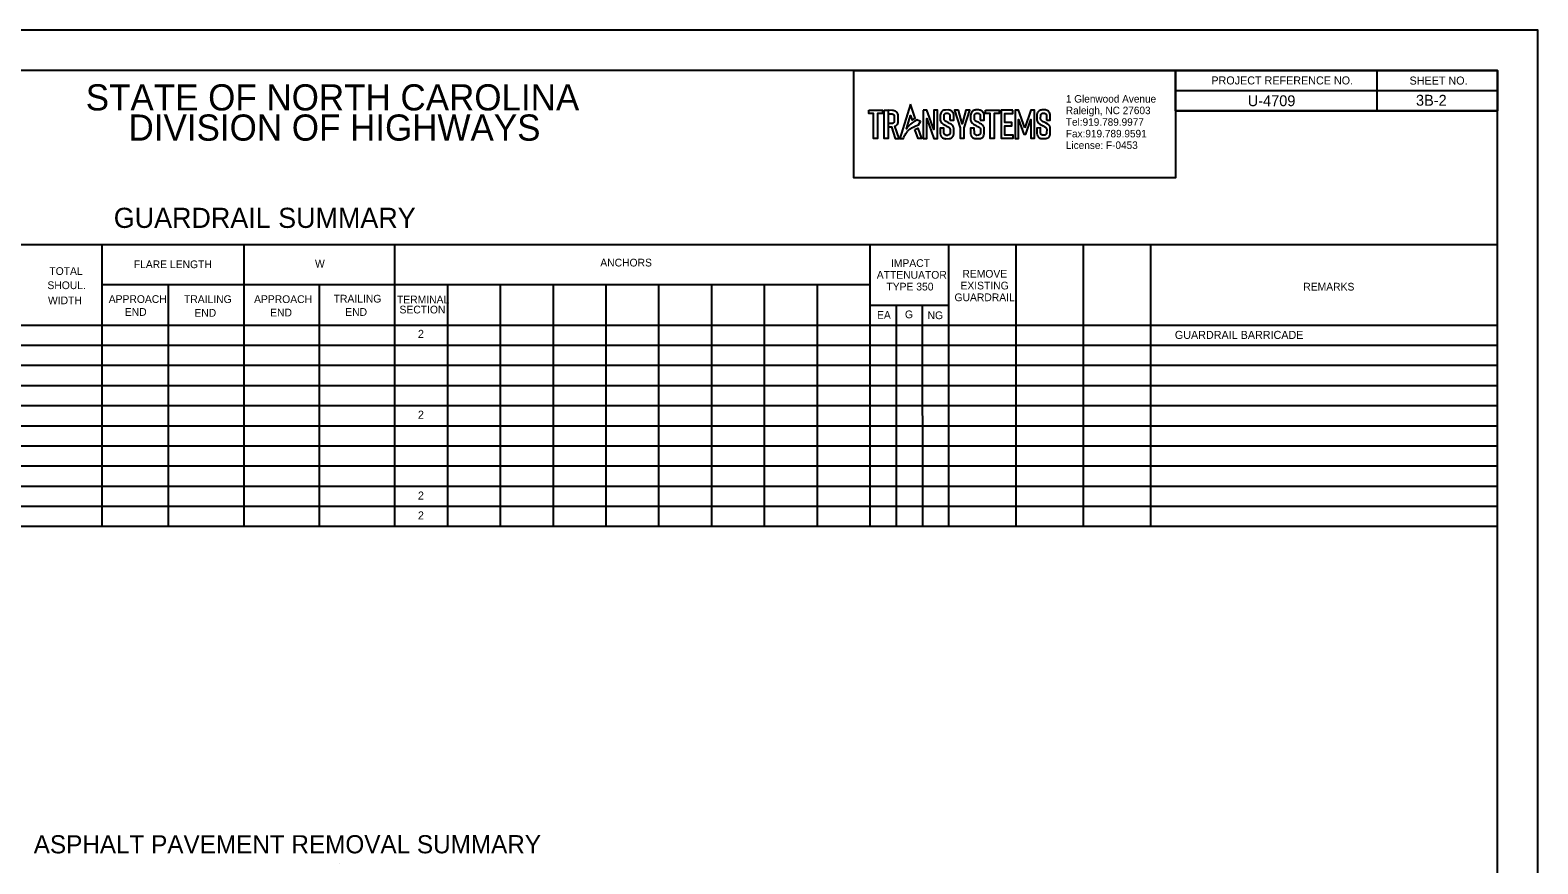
# Model space of a CAD drawing. Extents: x 573680 to 576464, y -53324 to -52224.
# Drawn here: x 574443 to 575380, y -52742 to -52224 of the extents above; entities that cross this region are included whole.
import ezdxf

# ---------------------------------------------------------------- set-up
doc = ezdxf.new("R2010")
doc.units = 0
for name, color, linetype in [('Old_Level_1', 7, 'Continuous'), ('Old_Level_2', 7, 'Continuous'), ('Old_Level_58', 7, 'Continuous'), ('Sheet Data Field CELL', 7, 'Continuous'), ('Sheet Plan And Profile CELL', 7, 'Continuous'), ('Sheet Plot Border Outside CELL', 7, 'Continuous'), ('Sheet Summary Combination CELL', 7, 'Continuous'), ('Sheet Summary Combination Grid CELL', 7, 'Continuous')]:
    doc.layers.add(name, color=color, linetype=linetype)

msp = doc.modelspace()

# ---------------------------------------------------------------- linework, layer by layer
at = {"layer": 'Old_Level_1'}
for points in [[(574990.11, -52270.23), (574983.45, -52291.56), (574985.67, -52291.55), (574986.01, -52290.71), (574986.59, -52289.55), (574986.9, -52288.92), (574987.27, -52288.39), (574987.8, -52287.63), (574988.12, -52287.16), (574988.5, -52286.77), (574988.88, -52286.37), (574989.37, -52285.88), (574989.78, -52285.61), (574990.2, -52285.27), (574990.75, -52284.95), (574991.25, -52284.67), (574992.46, -52284.1), (574993.46, -52283.69), (574995.11, -52283.13), (574996.24, -52280.99), (574994.07, -52280.04), (574992.43, -52280.92), (574991.06, -52281.83), (574990.08, -52282.62), (574989.55, -52283.05), (574989.02, -52283.62), (574988.48, -52284.18), (574988.08, -52284.61), (574987.71, -52285.26), (574987.5, -52285.62), (574990.13, -52277.24), (574991.12, -52280.13), (574993.02, -52278.87)], [(574964.15, -52274.08), (574972.62, -52274.07), (574972.62, -52276.14), (574969.51, -52276.15), (574969.52, -52291.57), (574967.17, -52291.57), (574967.16, -52276.04), (574964.19, -52276.05)], [(574973.77, -52274.08), (574976.09, -52274.08), (574976.1, -52291.64), (574973.79, -52291.65)], [(574976.09, -52276.16), (574978.48, -52276.16), (574978.78, -52276.21), (574979.18, -52276.38), (574979.5, -52276.59), (574979.74, -52276.87), (574979.89, -52277.2), (574980.01, -52277.45), (574980.01, -52278.03), (574980.02, -52280.52), (574979.96, -52280.85), (574979.88, -52281.3), (574979.75, -52281.59), (574979.55, -52281.85), (574979.28, -52282.07), (574978.85, -52282.22), (574978.53, -52282.26), (574978.2, -52282.3), (574976.09, -52282.31), (574976.1, -52284.42), (574978.21, -52284.41), (574980.58, -52291.57), (574983, -52291.55), (574980.35, -52284.01), (574980.73, -52283.87), (574981.26, -52283.47), (574981.75, -52282.94), (574982.1, -52282.31), (574982.31, -52281.67), (574982.3, -52281.49), (574982.34, -52276.92), (574982.14, -52276.18), (574981.77, -52275.5), (574981.36, -52275.03), (574980.66, -52274.55), (574979.99, -52274.33), (574979.31, -52274.1), (574978.9, -52274.1), (574976.09, -52274.08)], [(574997.88, -52274.04), (574997.9, -52291.5), (575000.13, -52291.5), (575000.12, -52279.22), (575004.58, -52291.53), (575006.83, -52291.5), (575006.8, -52273.99), (575004.63, -52274), (575004.64, -52285.98), (575000.24, -52274.04)], [(575014.58, -52280.22), (575016.89, -52280.21), (575016.89, -52276.74), (575016.69, -52276.03), (575016.41, -52275.44), (575016.11, -52275.05), (575015.74, -52274.7), (575015.3, -52274.42), (575014.88, -52274.24), (575014.88, -52274.24), (575014.42, -52274.05), (575013.94, -52273.93), (575013.62, -52273.85), (575011.87, -52273.88), (575011.34, -52273.97), (575010.88, -52274.05), (575010.42, -52274.29), (575010.01, -52274.5), (575009.62, -52274.79), (575009.31, -52275.1), (575009.07, -52275.47), (575008.87, -52275.86), (575008.62, -52276.56), (575008.57, -52277.07), (575008.57, -52280.24), (575008.68, -52280.72), (575008.91, -52281.21), (575009.2, -52281.62), (575009.5, -52281.93), (575009.95, -52282.28), (575010.4, -52282.63), (575010.69, -52282.85), (575011.17, -52283.07), (575011.65, -52283.3), (575012.04, -52283.55), (575012.48, -52283.84), (575013.01, -52284.11), (575013.44, -52284.32), (575013.87, -52284.64), (575014.18, -52284.93), (575014.43, -52285.17), (575014.59, -52285.65), (575014.68, -52285.95), (575014.65, -52288.19), (575014.49, -52288.67), (575014.24, -52289.09), (575013.91, -52289.38), (575013.56, -52289.54), (575013.22, -52289.62), (575012.25, -52289.64), (575011.93, -52289.55), (575011.6, -52289.35), (575011.27, -52289.16), (575011.13, -52288.82), (575010.99, -52288.49), (575010.88, -52288.22), (575010.84, -52285.11), (575008.5, -52285.14), (575008.55, -52288.85), (575008.66, -52289.13), (575008.93, -52289.99), (575009.11, -52290.28), (575009.36, -52290.6), (575009.74, -52290.98), (575010.05, -52291.17), (575010.48, -52291.35), (575010.64, -52291.42), (575011.07, -52291.6), (575011.6, -52291.65), (575012, -52291.69), (575014.14, -52291.64), (575014.73, -52291.5), (575015.56, -52291.12), (575015.84, -52291), (575016.46, -52290.21), (575016.79, -52289.42), (575016.95, -52288.71), (575016.9, -52285.29), (575016.89, -52284.81), (575016.76, -52284.44), (575016.57, -52284.08), (575016.03, -52283.33), (575015.32, -52282.77), (575014.34, -52282.19), (575013.6, -52281.75), (575012.14, -52280.98), (575011.38, -52280.42), (575011.05, -52280), (575010.98, -52279.71), (575010.9, -52279.43), (575010.94, -52277), (575011.07, -52276.74), (575011.19, -52276.49), (575011.37, -52276.33), (575011.6, -52276.14), (575011.86, -52276.03), (575012.12, -52275.92), (575012.27, -52275.95), (575012.28, -52275.88), (575013.24, -52275.89), (575013.52, -52276), (575013.79, -52276.11), (575014.07, -52276.22), (575014.2, -52276.42), (575014.39, -52276.69), (575014.48, -52276.97), (575014.57, -52277.25), (575014.56, -52277.55)], [(575019.85, -52274.03), (575017.31, -52274.04), (575020.93, -52284.92), (575020.96, -52291.46), (575023.35, -52291.45), (575023.32, -52284.96), (575026.98, -52273.99), (575024.49, -52274.06), (575022.18, -52282.4)], [(575033.45, -52280.2), (575035.76, -52280.2), (575035.76, -52276.72), (575035.56, -52276.01), (575035.28, -52275.42), (575034.98, -52275.03), (575034.61, -52274.68), (575034.17, -52274.4), (575033.75, -52274.22), (575033.75, -52274.22), (575033.29, -52274.03), (575032.81, -52273.91), (575032.49, -52273.83), (575030.74, -52273.87), (575030.21, -52273.96), (575029.75, -52274.04), (575029.29, -52274.28), (575028.89, -52274.49), (575028.49, -52274.77), (575028.18, -52275.08), (575027.94, -52275.45), (575027.74, -52275.84), (575027.49, -52276.54), (575027.44, -52277.06), (575027.44, -52280.23), (575027.56, -52280.7), (575027.78, -52281.2), (575028.07, -52281.61), (575028.37, -52281.92), (575028.82, -52282.26), (575029.27, -52282.61), (575029.56, -52282.83), (575030.04, -52283.06), (575030.52, -52283.28), (575030.91, -52283.53), (575031.36, -52283.82), (575031.88, -52284.09), (575032.32, -52284.31), (575032.75, -52284.62), (575033.06, -52284.92), (575033.31, -52285.15), (575033.46, -52285.64), (575033.55, -52285.93), (575033.52, -52288.17), (575033.36, -52288.65), (575033.11, -52289.07), (575032.78, -52289.37), (575032.43, -52289.53), (575032.09, -52289.6), (575031.13, -52289.62), (575030.8, -52289.53), (575030.48, -52289.33), (575030.15, -52289.14), (575030, -52288.81), (575029.86, -52288.47), (575029.75, -52288.2), (575029.71, -52285.09), (575027.37, -52285.12), (575027.42, -52288.83), (575027.54, -52289.11), (575027.81, -52289.97), (575027.98, -52290.27), (575028.23, -52290.58), (575028.61, -52290.96), (575028.92, -52291.15), (575029.35, -52291.33), (575029.51, -52291.4), (575029.94, -52291.58), (575030.48, -52291.64), (575030.87, -52291.67), (575033.01, -52291.62), (575033.6, -52291.48), (575034.43, -52291.11), (575034.71, -52290.98), (575035.33, -52290.19), (575035.67, -52289.4), (575035.82, -52288.69), (575035.77, -52285.27), (575035.76, -52284.8), (575035.63, -52284.42), (575035.44, -52284.07), (575034.9, -52283.31), (575034.19, -52282.75), (575033.22, -52282.17), (575032.47, -52281.73), (575031.01, -52280.96), (575030.25, -52280.4), (575029.93, -52279.98), (575029.85, -52279.69), (575029.77, -52279.41), (575029.82, -52276.98), (575029.94, -52276.72), (575030.06, -52276.47), (575030.24, -52276.32), (575030.47, -52276.12), (575030.73, -52276.01), (575030.99, -52275.91), (575031.14, -52275.94), (575031.15, -52275.86), (575032.11, -52275.88), (575032.39, -52275.99), (575032.67, -52276.1), (575032.94, -52276.21), (575033.07, -52276.4), (575033.26, -52276.68), (575033.35, -52276.95), (575033.44, -52277.23), (575033.44, -52277.53)], [(575036.61, -52274.01), (575045.08, -52274), (575045.08, -52276.08), (575041.97, -52276.08), (575041.98, -52291.5), (575039.63, -52291.5), (575039.62, -52275.98), (575036.65, -52275.98)], [(575053.68, -52274), (575046.3, -52274.01), (575046.31, -52291.44), (575053.78, -52291.43), (575053.78, -52289.46), (575048.74, -52289.46), (575048.73, -52283.62), (575052.95, -52283.62), (575052.95, -52281.54), (575048.69, -52281.54), (575048.69, -52276.05), (575053.7, -52276.04)], [(575061.06, -52284.85), (575057.25, -52273.93), (575055.03, -52274.04), (575055.12, -52291.5), (575057.23, -52291.49), (575057.17, -52279.81), (575060.44, -52288.8), (575061.79, -52288.83), (575064.85, -52279.7), (575064.9, -52291.42), (575067.18, -52291.41), (575067.11, -52273.99), (575064.81, -52274)], [(575074.58, -52280.16), (575076.9, -52280.16), (575076.89, -52276.68), (575076.7, -52275.98), (575076.42, -52275.39), (575076.12, -52275), (575075.75, -52274.64), (575075.31, -52274.36), (575074.88, -52274.19), (575074.88, -52274.19), (575074.42, -52273.99), (575073.94, -52273.87), (575073.62, -52273.79), (575071.87, -52273.83), (575071.34, -52273.92), (575070.88, -52274), (575070.42, -52274.24), (575070.02, -52274.45), (575069.62, -52274.73), (575069.31, -52275.05), (575069.07, -52275.41), (575068.88, -52275.81), (575068.62, -52276.5), (575068.57, -52277.02), (575068.57, -52280.19), (575068.69, -52280.66), (575068.92, -52281.16), (575069.21, -52281.57), (575069.5, -52281.88), (575069.95, -52282.23), (575070.41, -52282.57), (575070.69, -52282.79), (575071.17, -52283.02), (575071.66, -52283.24), (575072.05, -52283.5), (575072.49, -52283.78), (575073.02, -52284.05), (575073.45, -52284.27), (575073.88, -52284.58), (575074.19, -52284.88), (575074.44, -52285.12), (575074.59, -52285.6), (575074.69, -52285.9), (575074.65, -52288.13), (575074.49, -52288.62), (575074.24, -52289.04), (575073.92, -52289.33), (575073.56, -52289.49), (575073.22, -52289.56), (575072.26, -52289.58), (575071.94, -52289.49), (575071.61, -52289.3), (575071.28, -52289.1), (575071.14, -52288.77), (575070.99, -52288.43), (575070.88, -52288.17), (575070.84, -52285.05), (575068.51, -52285.08), (575068.55, -52288.79), (575068.67, -52289.07), (575068.94, -52289.93), (575069.11, -52290.23), (575069.37, -52290.55), (575069.75, -52290.92), (575070.05, -52291.11), (575070.49, -52291.3), (575070.64, -52291.36), (575071.07, -52291.54), (575071.61, -52291.6), (575072, -52291.64), (575074.14, -52291.58), (575074.74, -52291.44), (575075.56, -52291.07), (575075.84, -52290.94), (575076.46, -52290.15), (575076.8, -52289.36), (575076.95, -52288.65), (575076.9, -52285.23), (575076.89, -52284.76), (575076.76, -52284.38), (575076.57, -52284.03), (575076.03, -52283.27), (575075.32, -52282.71), (575074.35, -52282.13), (575073.6, -52281.69), (575072.14, -52280.92), (575071.39, -52280.36), (575071.06, -52279.94), (575070.98, -52279.66), (575070.9, -52279.37), (575070.95, -52276.94), (575071.07, -52276.69), (575071.2, -52276.43), (575071.37, -52276.28), (575071.61, -52276.08), (575071.86, -52275.98), (575072.12, -52275.87), (575072.27, -52275.9), (575072.29, -52275.82), (575073.24, -52275.84), (575073.52, -52275.95), (575073.8, -52276.06), (575074.08, -52276.17), (575074.21, -52276.36), (575074.39, -52276.64), (575074.48, -52276.91), (575074.58, -52277.19), (575074.57, -52277.5)], [(574992.73, -52285.93), (574994.64, -52285.17), (574996.91, -52291.61), (574994.81, -52291.53)]]:
    msp.add_lwpolyline(points, close=True, dxfattribs=at)
at = {"layer": 'Old_Level_58'}
msp.add_lwpolyline([(574954.76, -52249.31), (575154.81, -52249.31), (575154.81, -52316), (574954.76, -52316)], close=True, dxfattribs=at)
at = {"layer": 'Sheet Plan And Profile CELL'}
for points in [[(575354.86, -52249.31), (573854.86, -52249.31), (573854.86, -53299.31), (575354.86, -53299.31)], [(575154.81, -52249.31), (575354.86, -52249.31), (575354.86, -52274.36), (575154.81, -52274.36)]]:
    msp.add_lwpolyline(points, close=True, dxfattribs=at)
at = {"layer": 'Sheet Plot Border Outside CELL'}
msp.add_lwpolyline([(573679.86, -53324.31), (575379.86, -53324.31), (575379.86, -52224.31), (573679.86, -52224.31)], close=True, dxfattribs=at)
at = {"layer": 'Sheet Summary Combination CELL'}
for p, q in [((575279.86, -52249.36), (575279.86, -52274.36)), ((575154.81, -52261.86), (575354.86, -52261.86)), ((575154.81, -52274.36), (575354.86, -52274.36)), ((574635.06, -52741.93), (574635.06, -52741.93))]:
    msp.add_line(p, q, dxfattribs=at)
msp.add_lwpolyline([(575154.81, -52249.31), (575354.86, -52249.31), (575354.86, -52274.36), (575154.81, -52274.36)], close=True, dxfattribs=at)
at = {"layer": 'Sheet Summary Combination Grid CELL'}
for p, q in [((573854.86, -52357.39), (575354.86, -52357.39)), ((574487.66, -52357.39), (574487.66, -52532.39)), ((574575.76, -52357.39), (574575.76, -52532.39)), ((574669.51, -52357.39), (574669.51, -52532.39)), ((574964.81, -52357.39), (574964.81, -52532.39)), ((575013.66, -52357.39), (575013.66, -52532.39)), ((575055.46, -52357.39), (575055.46, -52532.39)), ((575097.26, -52357.39), (575097.26, -52532.39)), ((575139.11, -52357.39), (575139.11, -52532.39)), ((574964.81, -52382.39), (574487.66, -52382.39)), ((574528.86, -52382.39), (574528.86, -52532.39)), ((574622.61, -52382.39), (574622.61, -52532.39)), ((574702.31, -52382.39), (574702.31, -52532.39)), ((574735.11, -52382.39), (574735.11, -52532.39)), ((574767.96, -52382.39), (574767.96, -52532.39)), ((574800.76, -52382.39), (574800.76, -52532.39)), ((574833.56, -52382.39), (574833.56, -52532.39)), ((574866.36, -52382.39), (574866.36, -52532.39)), ((574899.21, -52382.39), (574899.21, -52532.39)), ((574932.01, -52382.39), (574932.01, -52532.39)), ((574964.81, -52395.14), (575013.41, -52395.14)), ((574981.06, -52395.14), (574981.14, -52532.39)), ((574997.41, -52395.14), (574997.49, -52532.39)), ((573854.86, -52407.39), (575354.86, -52407.39)), ((573854.86, -52419.89), (575354.86, -52419.89)), ((573854.86, -52432.39), (575354.86, -52432.39)), ((573854.86, -52444.89), (575354.86, -52444.89)), ((573854.86, -52457.39), (575354.86, -52457.39)), ((573854.86, -52457.39), (575354.86, -52457.39)), ((573854.86, -52469.89), (575354.86, -52469.89)), ((573854.86, -52469.89), (575354.86, -52469.89)), ((573854.86, -52482.39), (575354.86, -52482.39)), ((573854.86, -52494.89), (575354.86, -52494.89)), ((573854.86, -52507.39), (575354.86, -52507.39)), ((573854.86, -52507.39), (575354.86, -52507.39)), ((573854.86, -52519.89), (575354.86, -52519.89)), ((573854.86, -52519.89), (575354.86, -52519.89)), ((573854.86, -52532.39), (575354.86, -52532.39)), ((573854.86, -52532.39), (575354.86, -52532.39))]:
    msp.add_line(p, q, dxfattribs=at)

# ---------------------------------------------------------------- texts
at = {"layer": 'Old_Level_2'}
for s, p in [('1 Glenwood Avenue', (575086.61, -52269.28)), ('Raleigh, NC 27603', (575086.61, -52276.47)), ('Tel:919.789.9977 ', (575086.61, -52283.67)), ('Fax:919.789.9591', (575086.61, -52290.87)), ('License: F-0453', (575086.61, -52298.06))]:
    msp.add_text(s, height=4.6576, rotation=360, dxfattribs=at).set_placement(p)
at = {"layer": 'Sheet Data Field CELL'}
for s, p in [('U-4709', (575199.61, -52271.51)), ('3B-2', (575304.16, -52271.21))]:
    msp.add_text(s, height=6.75, dxfattribs=at).set_placement(p)
at = {"layer": 'Sheet Plan And Profile CELL'}
for s, height, p in [('PROJECT REFERENCE NO.', 5.0001, (575177.01, -52258.01)), ('SHEET NO.', 5, (575300.16, -52258.11))]:
    msp.add_text(s, height=height, rotation=360, dxfattribs=at).set_placement(p)
at = {"layer": 'Sheet Summary Combination CELL'}
for s, height, p in [('PROJECT REFERENCE NO.', 5.0001, (575177.01, -52258.01)), ('SHEET NO.', 5, (575300.16, -52258.11)), ('STATE OF NORTH CAROLINA', 16.2501, (574477.61, -52274.16)), ('DIVISION OF HIGHWAYS', 16.2501, (574504.21, -52292.91)), ('GUARDRAIL SUMMARY', 12.5001, (574495.01, -52347.09)), ('ANCHORS', 4.8, (574797.31, -52371.04)), ('IMPACT', 4.8, (574977.91, -52371.34)), ('TOTAL', 4.8, (574455.01, -52376.29)), ('FLARE LENGTH', 4.8, (574507.46, -52372.09)), ('W', 4.8, (574620.06, -52371.69)), ('ATTENUATOR', 4.8, (574969.11, -52378.64)), ('REMOVE', 4.8, (575022.31, -52377.99)), ('SHOUL.', 4.8, (574453.81, -52385.09)), ('TYPE 350', 4.8, (574975.11, -52385.94)), ('EXISTING', 4.8, (575021.11, -52385.29)), ('REMARKS', 4.8, (575234.11, -52385.99)), ('WIDTH', 4.8, (574454.16, -52394.49)), ('APPROACH', 4.8, (574491.91, -52393.69)), ('TRAILING', 4.8, (574538.66, -52393.74)), ('APPROACH', 4.8, (574582.21, -52393.74)), ('TRAILING', 4.8, (574631.66, -52393.44)), ('TERMINAL', 4.8, (574671.01, -52393.96)), ('GUARDRAIL', 4.8, (575017.41, -52392.59)), ('END', 4.8, (574501.91, -52401.69)), ('END', 4.8, (574545.11, -52402.24)), ('END', 4.8, (574592.21, -52402.04)), ('END', 4.8, (574638.86, -52401.69)), ('SECTION', 4.8, (574672.57, -52400.2)), ('EA', 4.8, (574969.26, -52403.54)), ('G', 4.8, (574986.61, -52403.19)), ('NG', 4.8, (575000.66, -52403.74)), ('2', 5, (574684.02, -52415.4)), ('GUARDRAIL BARRICADE', 5.0001, (575154.33, -52416.03)), ('2', 5, (574684.02, -52465.59)), ('2', 5, (574684.02, -52515.78)), ('2', 5, (574684.02, -52528.12))]:
    msp.add_text(s, height=height, dxfattribs=at).set_placement(p)
msp.add_text('ASPHALT PAVEMENT REMOVAL SUMMARY', height=11.2813, rotation=0.01193, dxfattribs=at).set_placement((574445.3, -52735.48))

doc.saveas('drawing.dxf')
